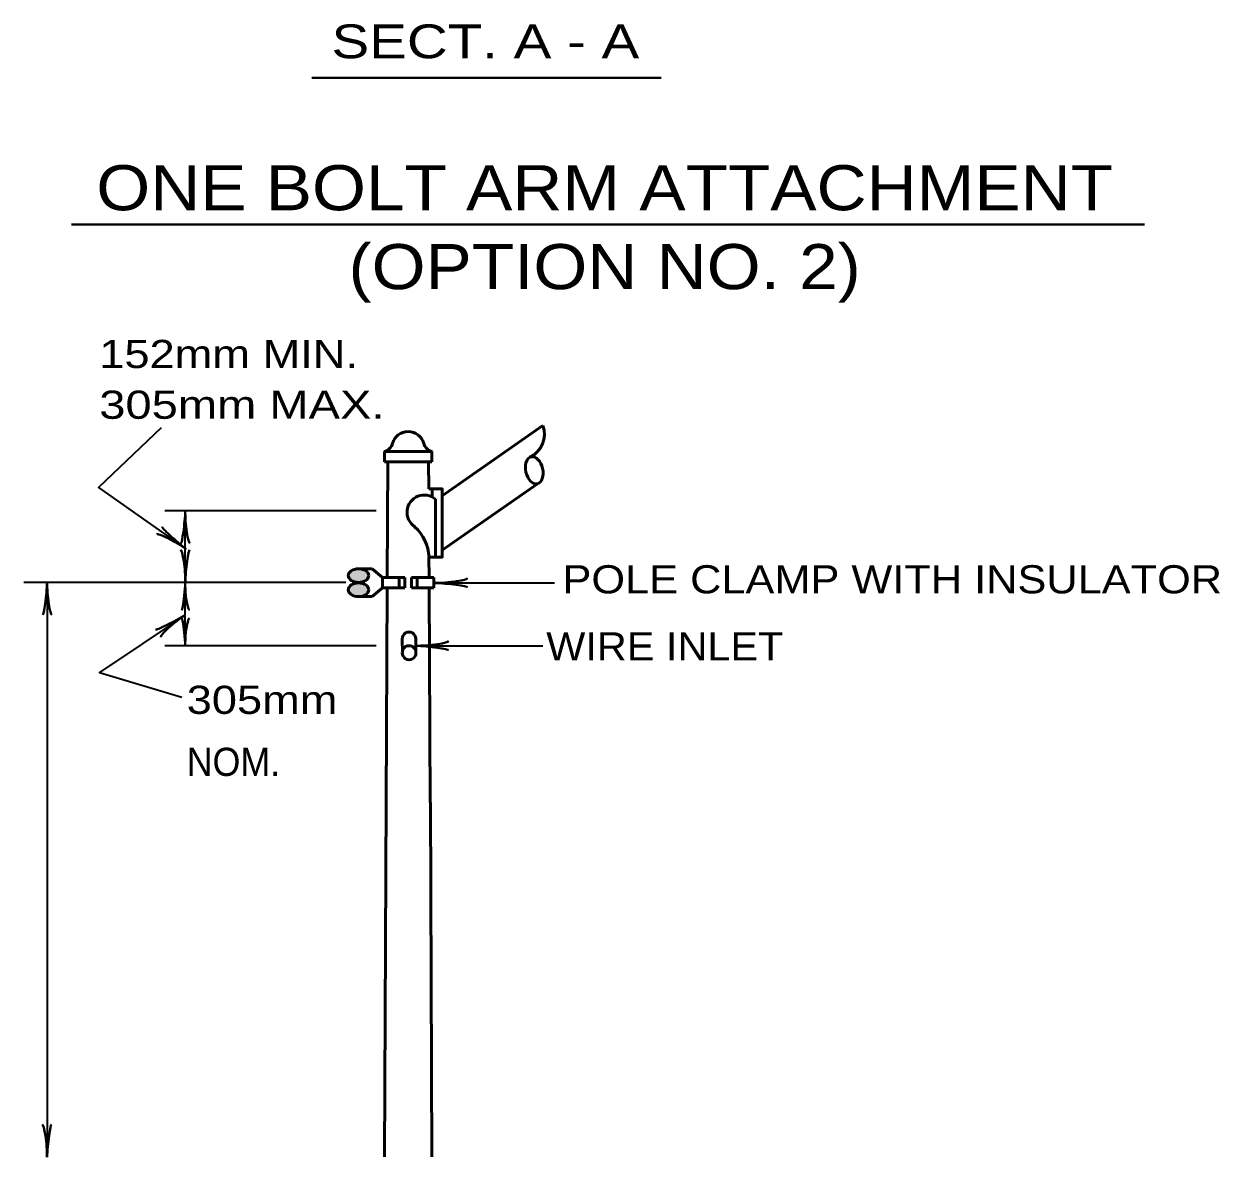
# Model space of a CAD drawing. Extents: x 6460 to 7173, y 270 to 723.
# Drawn here: x 6824.6 to 6930.7, y 463.4 to 563.9 of the extents above; entities that cross this region are included whole.
import ezdxf
from ezdxf.enums import TextEntityAlignment as Align

# ---------------------------------------------------------------- set-up
doc = ezdxf.new("R2010")
doc.units = 0
doc.layers.add('1', color=7, linetype='Continuous', lineweight=35)

msp = doc.modelspace()

# ---------------------------------------------------------------- hatches: boundary and pattern name
at = {"layer": '1'}
h = msp.add_hatch(color=256, dxfattribs=at)
edge = h.paths.add_edge_path()
edge.add_ellipse((6854.294, 514.969), major_axis=(0.907, 0), ratio=0.6666667, start_angle=0, end_angle=360)
h = msp.add_hatch(color=256, dxfattribs=at)
edge = h.paths.add_edge_path()
edge.add_ellipse((6854.294, 513.717), major_axis=(0.907, 0), ratio=0.6666667, start_angle=0, end_angle=360)

# ---------------------------------------------------------------- linework, layer by layer
at = {"layer": '1', "lineweight": 40}
for p, q in [((6850.157, 559.125), (6881.136, 559.125)), ((6828.823, 546.105), (6924.037, 546.105))]:
    msp.add_line(p, q, dxfattribs=at)
at = {"layer": '1', "lineweight": 53}
for p, q in [((6861.725, 522.056), (6870.645, 528.296)), ((6856.586, 525.976), (6860.805, 525.976)), ((6856.586, 525.976), (6856.586, 525.076)), ((6860.805, 525.976), (6860.805, 525.076)), ((6856.586, 525.076), (6860.805, 525.076)), ((6856.885, 525.076), (6856.825, 514.796)), ((6860.506, 525.076), (6860.525, 522.656)), ((6860.825, 522.656), (6860.825, 521.956)), ((6861.725, 517.216), (6870.166, 523.116)), ((6861.126, 521.756), (6861.126, 516.616)), ((6860.546, 516.616), (6860.565, 514.796)), ((6855.506, 515.576), (6854.285, 515.576)), ((6856.425, 514.796), (6855.506, 515.576)), ((6856.425, 514.796), (6858.405, 514.796)), ((6856.425, 514.796), (6856.425, 513.896)), ((6857.905, 514.796), (6857.905, 513.896)), ((6858.405, 514.796), (6858.405, 513.896)), ((6859.006, 514.796), (6860.965, 514.796)), ((6859.006, 514.796), (6859.006, 513.896)), ((6859.485, 514.796), (6859.485, 513.896)), ((6860.965, 514.796), (6860.965, 513.896)), ((6856.425, 513.896), (6855.506, 513.116)), ((6856.425, 513.896), (6858.405, 513.896)), ((6856.825, 513.896), (6856.586, 463.396)), ((6859.006, 513.896), (6860.965, 513.896)), ((6860.565, 513.896), (6860.653, 494.836)), ((6855.506, 513.116), (6854.285, 513.116)), ((6858.166, 509.336), (6858.185, 508.136)), ((6859.385, 509.356), (6859.385, 508.136)), ((6860.666, 494.836), (6860.805, 463.396))]:
    msp.add_line(p, q, dxfattribs=at)
at = {"layer": '1'}
for p, q in [((6855.86, 520.725), (6837.093, 520.725)), ((6853.173, 514.363), (6824.602, 514.363)), ((6826.656, 514.363), (6826.656, 463.396)), ((6861.097, 514.318), (6871.694, 514.318)), ((6855.86, 508.751), (6837.093, 508.751)), ((6859.408, 508.743), (6870.639, 508.743))]:
    msp.add_line(p, q, dxfattribs=at)
for points in [[(6836.785, 528.081), (6831.219, 522.801), (6838.993, 517.329)], [(6838.92, 508.751), (6838.92, 514.363), (6838.92, 520.725)], [(6838.897, 511.472), (6831.315, 506.384), (6838.609, 504.176)]]:
    msp.add_lwpolyline(points, dxfattribs=at)
at = {"layer": '1', "lineweight": 53}
msp.add_lwpolyline([(6860.525, 522.656), (6861.725, 522.656), (6861.725, 516.616), (6860.546, 516.616)], dxfattribs=at)
for centre, radius, start, end in [((6858.698, 526.299), 1.453, 16.19781, 163.80219), ((6868.526, 527.521), 2.264, 295.32486, 20.09191), ((6856.388, 526.901), 0.936, 281.94387, 347.91984), ((6861.009, 526.901), 0.936, 192.08016, 258.05613), ((6860.13, 520.587), 1.535, 49.39069, 236.15933), ((6856.578, 516.382), 3.982, 3.29768, 47.3671), ((6858.775, 509.36), 0.605, 358.85054, 181.71286), ((6858.781, 508.15), 0.605, 358.85054, 181.71286), ((6858.781, 508.114), 0.605, 178.28714, 1.14946)]:
    msp.add_arc(centre, radius, start, end, dxfattribs=at)
for centre, major_axis, ratio in [((6869.886, 524.309), (-0.27, 1.196), 0.618585), ((6854.294, 514.969), (0.907, 0), 0.666667), ((6854.294, 513.717), (0.907, 0), 0.666667)]:
    msp.add_ellipse(centre, major_axis=major_axis, ratio=ratio, dxfattribs=at)
at = {"layer": '1', "lineweight": 40}
for centre, major_axis, ratio, start_param, end_param in [((6838.711, 519.596), (0.176, 1.756), 0.07063, 3.1407148, 5.41811), ((6839.188, 519.625), (-0.156, 1.786), 0.122415, 0.8963533, 3.1415927), ((6838.198, 518.147), (-1.335, 1.155), 0.07063, 6.2823074, 8.5597026), ((6837.941, 517.731), (1.55, -0.9), 0.122415, 0.8963533, 3.1415927), ((6838.652, 515.463), (0.156, -1.786), 0.122415, 0.8963533, 3.1415927), ((6839.128, 515.493), (-0.176, -1.756), 0.07063, 3.1407148, 5.41811), ((6826.444, 513.243), (0.176, 1.756), 0.07063, 3.1407148, 5.41811), ((6826.444, 513.243), (0.176, 1.756), 0.07063, 3.1407148, 5.41811), ((6826.932, 513.272), (-0.156, 1.786), 0.122415, 0.8963533, 3.1415927), ((6826.932, 513.272), (-0.156, 1.786), 0.122415, 0.8963533, 3.1415927), ((6838.711, 513.233), (0.176, 1.756), 0.07063, 4.6860792, 5.41811), ((6839.191, 513.254), (-0.156, 1.786), 0.122415, 0.8963533, 1.5991095), ((6862.188, 514.594), (-1.786, -0.156), 0.122415, 0.8963533, 3.1415927), ((6862.188, 514.594), (-1.786, -0.156), 0.122415, 0.8963533, 3.1415927), ((6862.218, 514.106), (-1.756, 0.176), 0.07063, 3.1407148, 5.41811), ((6862.218, 514.106), (-1.756, 0.176), 0.07063, 3.1407148, 5.41811), ((6838.76, 513.671), (0.176, 1.756), 0.07063, 3.1407148, 4.4333261), ((6839.142, 513.711), (-0.156, 1.786), 0.122415, 1.8592897, 3.1415927), ((6837.848, 511.024), (1.556, 0.833), 0.07063, 3.1407148, 5.41811), ((6838.145, 510.635), (1.396, 1.125), 0.122415, 0.8963533, 3.1415927), ((6838.76, 509.444), (0.176, -1.756), 0.07063, 1.8498592, 3.1424706), ((6839.142, 509.404), (-0.156, -1.786), 0.122415, 3.1415927, 4.4238957), ((6838.711, 509.881), (0.176, -1.756), 0.07063, 0.8650754, 1.5971061), ((6839.191, 509.861), (-0.156, -1.786), 0.122415, 4.6840758, 5.386832), ((6860.499, 509.019), (-1.786, -0.156), 0.122415, 0.8963533, 3.1415927), ((6860.499, 509.019), (-1.786, -0.156), 0.122415, 0.8963533, 3.1415927), ((6860.529, 508.531), (-1.756, 0.176), 0.07063, 3.1407148, 5.41811), ((6860.529, 508.531), (-1.756, 0.176), 0.07063, 3.1407148, 5.41811), ((6826.379, 464.487), (0.156, -1.786), 0.122415, 0.8963533, 3.1415927), ((6826.379, 464.487), (0.156, -1.786), 0.122415, 0.8963533, 3.1415927), ((6826.867, 464.517), (-0.176, -1.756), 0.07063, 3.1407148, 5.41811), ((6826.867, 464.517), (-0.176, -1.756), 0.07063, 3.1407148, 5.41811)]:
    msp.add_ellipse(centre, major_axis=major_axis, ratio=ratio, start_param=start_param, end_param=end_param, dxfattribs=at)

# ---------------------------------------------------------------- texts
at = {"layer": '1'}
for s, height, width, p in [('SECT. A - A', 3, 1.25, (6851.898, 560.867)), ('152mm MIN.', 2.5, 1.2, (6831.287, 533.381)), ('305mm MAX.', 2.5, 1.25, (6831.287, 528.881)), ('POLE CLAMP WITH INSULATOR', 2.5, 1.15, (6872.391, 513.392)), ('WIRE INLET', 2.5, 1.1, (6870.951, 507.44)), ('305mm', 2.5, 1.2, (6839.045, 502.7)), ('NOM.', 2.5, 0.95, (6839.045, 497.2))]:
    msp.add_text(s, height=height, dxfattribs=dict(at, width=width)).set_placement(p)
at = {"layer": '1', "width": 1.15}
for s, p in [('ONE BOLT ARM ATTACHMENT', (6876.135, 547.382)), ('(OPTION NO. 2)', (6876.134, 540.382))]:
    msp.add_text(s, height=4, dxfattribs=at).set_placement(p, align=Align.CENTER)

doc.saveas('drawing.dxf')
